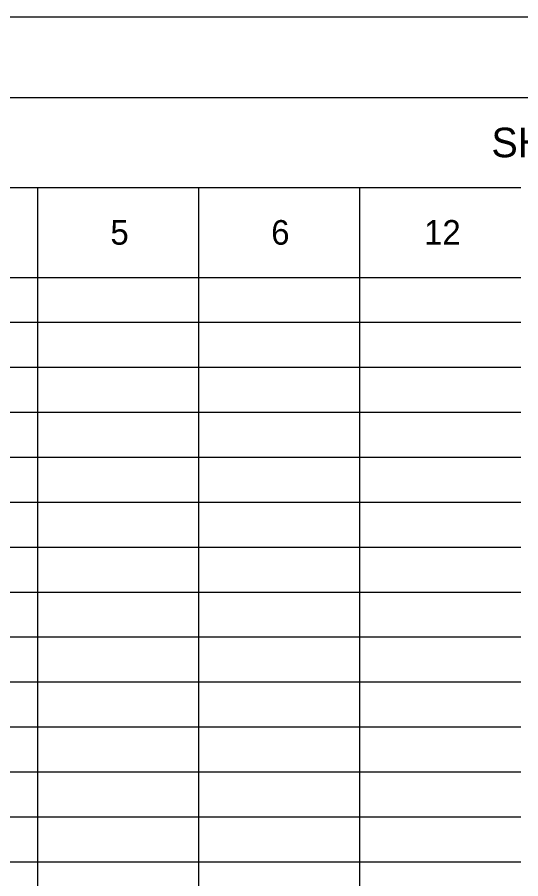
# Model space of a CAD drawing. Extents: x 0 to 34, y 0 to 22.
# Drawn here: x 3.38 to 6.51, y 16.63 to 22 of the extents above; entities that cross this region are included whole.
import ezdxf

# ---------------------------------------------------------------- set-up
doc = ezdxf.new("R2010")
doc.units = 0
for name, color, linetype in [('SH_Border', 7, 'Continuous'), ('SH_Cut_Line', 7, 'Continuous'), ('SH_Text', 7, 'Continuous')]:
    doc.layers.add(name, color=color, linetype=linetype)

msp = doc.modelspace()

# ---------------------------------------------------------------- linework, layer by layer
at = {"layer": 'SH_Border'}
msp.add_lwpolyline([(1.5, 21.5), (33.5, 21.5), (33.5, 0.5), (1.5, 0.5)], close=True, dxfattribs=at)
at = {"layer": 'SH_Cut_Line'}
msp.add_lwpolyline([(0, 0), (34, 0), (34, 22), (0, 22)], close=True, dxfattribs=at)
at = {"layer": 'SH_Text'}
for p, q in [((1.5, 21.5), (6.5126, 21.5)), ((1.5, 20.94), (6.5126, 20.94)), ((3.5051, 20.94), (3.5051, 20.66)), ((4.5076, 20.94), (4.5076, 20.66)), ((5.5101, 20.94), (5.5101, 20.66)), ((3.5051, 20.66), (3.5051, 20.38)), ((4.5076, 20.66), (4.5076, 20.38)), ((5.5101, 20.66), (5.5101, 20.38)), ((1.5, 20.38), (6.5126, 20.38)), ((3.5051, 20.38), (3.5051, 20.1)), ((4.5076, 20.38), (4.5076, 20.1)), ((5.5101, 20.38), (5.5101, 20.1)), ((1.5, 20.1), (6.5126, 20.1)), ((3.5051, 20.1), (3.5051, 18.7)), ((4.5076, 20.1), (4.5076, 18.7)), ((5.5101, 20.1), (5.5101, 18.7)), ((1.5, 19.82), (6.5126, 19.82)), ((1.5, 19.54), (6.5126, 19.54)), ((1.5, 19.26), (6.5126, 19.26)), ((1.5, 18.98), (6.5126, 18.98)), ((1.5, 18.7), (6.5126, 18.7)), ((3.5051, 18.7), (3.5051, 18.14)), ((4.5076, 18.7), (4.5076, 18.14)), ((5.5101, 18.7), (5.5101, 18.14)), ((1.5, 18.42), (6.5126, 18.42)), ((1.5, 18.14), (6.5126, 18.14)), ((3.5051, 18.14), (3.5051, 17.86)), ((4.5076, 18.14), (4.5076, 17.86)), ((5.5101, 18.14), (5.5101, 17.86)), ((1.5, 17.86), (6.5126, 17.86)), ((3.5051, 17.86), (3.5051, 17.58)), ((4.5076, 17.86), (4.5076, 17.58)), ((5.5101, 17.86), (5.5101, 17.58)), ((1.5, 17.58), (6.5126, 17.58)), ((3.5051, 17.58), (3.5051, 17.3)), ((4.5076, 17.58), (4.5076, 17.3)), ((5.5101, 17.58), (5.5101, 17.3)), ((1.5, 17.3), (6.5126, 17.3)), ((3.5051, 17.3), (3.5051, 17.02)), ((4.5076, 17.3), (4.5076, 17.02)), ((5.5101, 17.3), (5.5101, 17.02)), ((1.5, 17.02), (6.5126, 17.02)), ((3.5051, 17.02), (3.5051, 16.74)), ((4.5076, 17.02), (4.5076, 16.74)), ((5.5101, 17.02), (5.5101, 16.74)), ((1.5, 16.74), (6.5126, 16.74)), ((3.5051, 16.74), (3.5051, 16.18)), ((4.5076, 16.74), (4.5076, 16.18)), ((5.5101, 16.74), (5.5101, 16.18))]:
    msp.add_line(p, q, dxfattribs=at)

# ---------------------------------------------------------------- texts
for s, height, p in [('SHEET NUM.', 0.184, (6.33, 21.128)), ('5', 0.1533, (3.9594, 20.5833)), ('6', 0.1533, (4.9599, 20.5833)), ('12', 0.15333, (5.911, 20.5833))]:
    msp.add_text(s, height=height, dxfattribs=at).set_placement(p)

doc.saveas('drawing.dxf')
